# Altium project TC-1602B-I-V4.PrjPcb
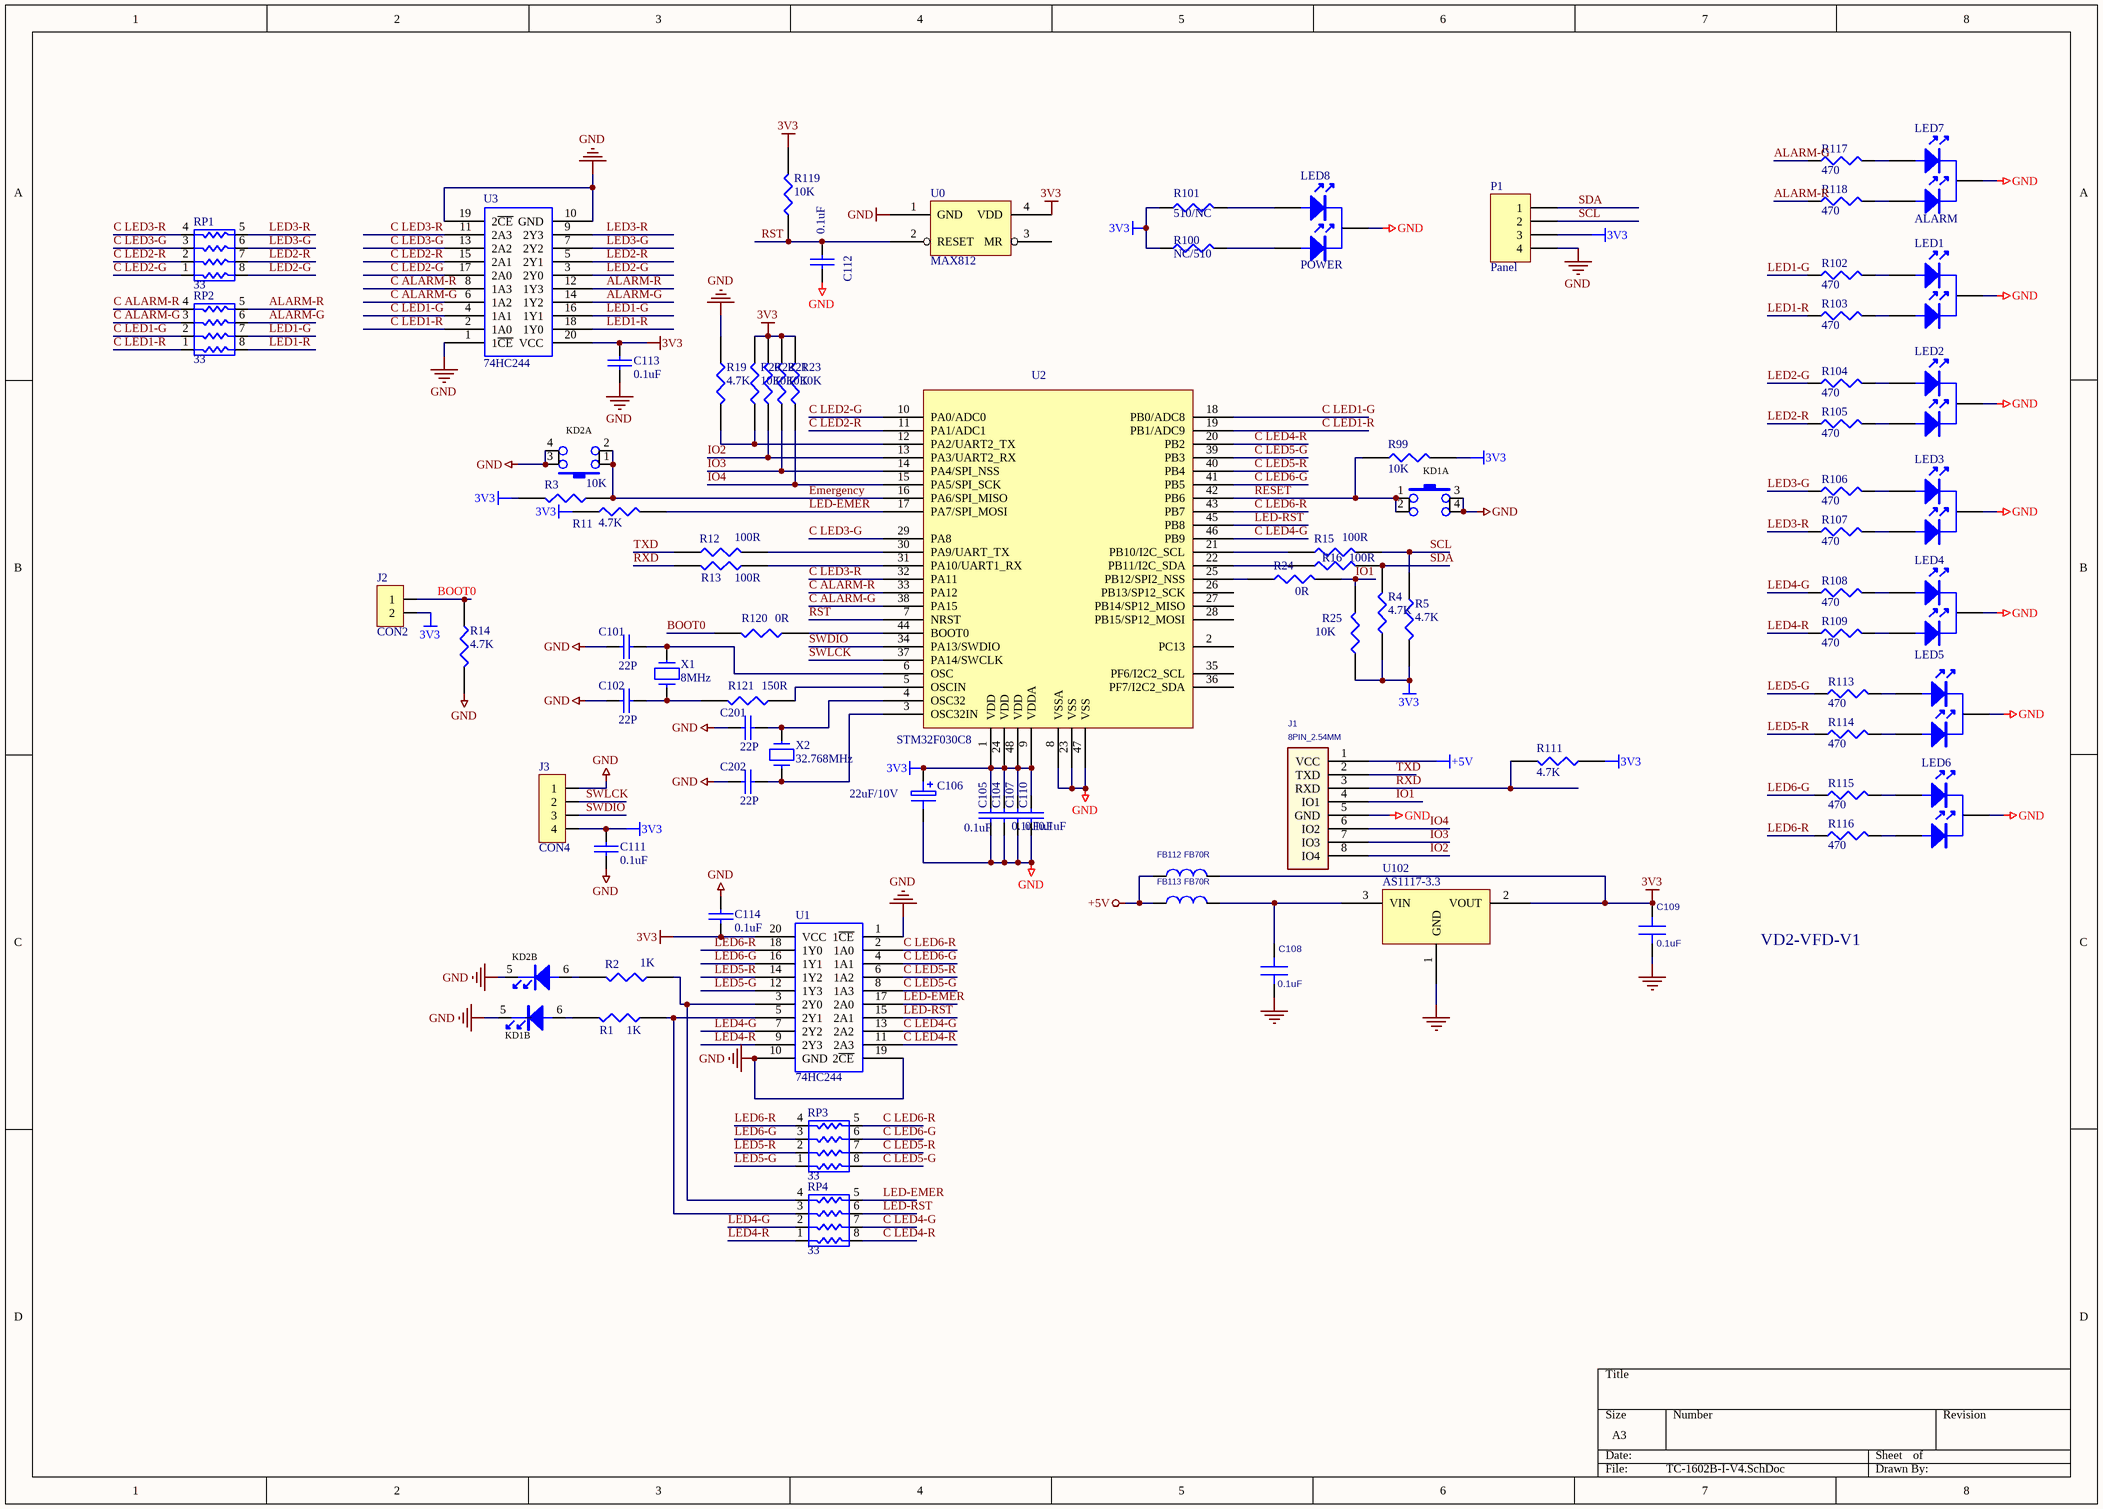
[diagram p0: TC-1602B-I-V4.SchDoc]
1 sheet, 81 parts. Net scope: global (net labels, ports and power ports of the same name join across sheets).

## Sheet TC-1602B-I-V4.SchDoc
size A3; SheetNumber: 0; SheetTotal: 0

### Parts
C101  22P  [C0603]
C102  22P  [C0603]
C104  0.1uF  [C0603]
C105  0.1uF  [C0603]
C106  22uF/10V  [C1206]
C107  0.1uF  [C0603]
C108  0.1uF  [C0402]
C109  0.1uF  [C0603]
C110  0.1uF  [C0603]
C111  0.1uF  [C0603]
C112  0.1uF  [C0603]
C113  0.1uF  [C0603]
C114  0.1uF  [C0603]
C201  22P  [C0402]
C202  22P  [C0402]
FB112  FB70R  [FB0603]
FB113  FB70R  [FB0603]
J1  8PIN_2.54MM  [CON8_2D54MM_G]
J2  CON2  [TJC3-2]
J3  CON4  [TJC3-4]
KD1  RESET  [SW6X6LED1]  (value not drawn)  (parts A,B of 2)
KD2  RESET  [SW6X6LED1]  (value not drawn)  (parts A,B of 2)
LED1  (no value)  [SIP3]
LED2  (no value)  [SIP3]
LED3  (no value)  [SIP3]
LED4  (no value)  [SIP3]
LED5  (no value)  [SIP3]
LED6  (no value)  [SIP3]
LED7  ALARM  [SIP3]
LED8  POWER  [SIP3]
P1  Panel  [Panel]
R1  1K  [R0603]
R2  1K  [R0603]
R3  10K  [R0603]
R4  4.7K  [R0603]
R5  4.7K  [R0603]
R11  4.7K  [R0603]
R12  100R  [R0603]
R13  100R  [R0603]
R14  4.7K  [R0603]
R15  100R  [R0603]
R16  100R  [R0603]
R19  4.7K  [R0603]
R20  10K  [R0603]
R21  10K  [R0603]
R22  10K  [R0603]
R23  10K  [R0603]
R24  0R  [R0603]
R25  10K  [R0603]
R99  10K  [R0603]
R100  NC/510  [R0603]
R101  510/NC  [R0603]
R102  470  [R0603]
R103  470  [R0603]
R104  470  [R0603]
R105  470  [R0603]
R106  470  [R0603]
R107  470  [R0603]
R108  470  [R0603]
R109  470  [R0603]
R111  4.7K  [R0603]
R113  470  [R0603]
R114  470  [R0603]
R115  470  [R0603]
R116  470  [R0603]
R117  470  [R0603]
R118  470  [R0603]
R119  10K  [R0603]
R120  0R  [R0603]
R121  150R  [R0603]
RP1  33  [RP0603]
RP2  33  [RP0603]
RP3  33  [RP0603]
RP4  33  [RP0603]
U0  MAX812  [SOT-143]
U1  74HC244  [SSOP-20]
U2  STM32F030C8  [QFN-48P-ATBM8869]
U3  74HC244  [SSOP-20]
U102  AS1117-3.3  [SOT-223]
X1  8MHz  [X-HC-49S]
X2  32.768MHz  [X-DT38]

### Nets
3V3: C104.1 C105.1 C106.1 C107.1 C109.1 C110.1 C111.1 C113.2 C114.1 FB112.2 J2.2 J3.4 P1.3 R3.2 R4.1 R5.2 R11.1 R20.2 R21.2 R22.2 R23.2 R25.1 R99.2 R100.1 R101.1 R111.1 R119.2 U0.4(VDD) U1.20(VCC) U2.1(VDD) U2.9(VDDA) U2.24(VDD) U2.48(VDD) U3.20(VCC) U102.2(VOUT)
+5V: FB112.1 FB113.1 J1.1(VCC)
GND: C101.1 C102.1 C104.2 C105.2 C106.2 C107.2 C108.2 C109.2 C110.2 C111.2 C112.2 C113.1 C114.2 C201.1 C202.1 J1.5(GND) J3.1 KD1.3 KD1.4 KD1.5 KD2.3 KD2.4 KD2.5 LED1.2 LED2.2 LED3.2 LED4.2 LED5.2 LED6.2 LED7.2 LED8.2 P1.4 R14.2 R19.1 U0.1(GND) U1.1(1~{CE}) U1.10(GND) U1.19(2~{CE}) U2.8(VSSA) U2.23(VSS) U2.47(VSS) U3.1(1~{CE}) U3.10(GND) U3.19(2~{CE}) U102.1(GND)
ALARM-G: R117.1 RP2.6 U3.14(1Y2)
ALARM-R: R118.1 RP2.5 U3.12(1Y3)
BOOT0: J2.1 R14.1 R120.2
C ALARM-G: RP2.3 U2.38(PA15) U3.6(1A2)
C ALARM-R: RP2.4 U2.33(PA12) U3.8(1A3)
C LED1-G: RP2.2 U2.18(PB0/ADC8) U3.4(1A1)
C LED1-R: RP2.1 U2.19(PB1/ADC9) U3.2(1A0)
C LED2-G: RP1.1 U2.10(PA0/ADC0) U3.17(2A0)
C LED2-R: RP1.2 U2.11(PA1/ADC1) U3.15(2A1)
C LED3-G: RP1.3 U2.29(PA8) U3.13(2A2)
C LED3-R: RP1.4 U2.32(PA11) U3.11(2A3)
C LED4-G: RP4.7 U1.13(2A2) U2.46(PB9)
C LED4-R: RP4.8 U1.11(2A3) U2.20(PB2)
C LED5-G: RP3.8 U1.8(1A3) U2.39(PB3)
C LED5-R: RP3.7 U1.6(1A2) U2.40(PB4)
C LED6-G: RP3.6 U1.4(1A1) U2.41(PB5)
C LED6-R: RP3.5 U1.2(1A0) U2.43(PB7)
Emergency: KD2.1 KD2.2 R3.1 U2.16(PA6/SPI_MISO)
IO1: J1.4(IO1) R24.2 R25.2
IO2: J1.8(IO4) R22.1 U2.13(PA3/UART2_RX)
IO3: J1.7(IO3) R21.1 U2.14(PA4/SPI_NSS)
IO4: J1.6(IO2) R23.1 U2.15(PA5/SPI_SCK)
LED1-G: R102.1 RP2.7 U3.16(1Y1)
LED1-R: R103.1 RP2.8 U3.18(1Y0)
LED2-G: R104.1 RP1.8 U3.3(2Y0)
LED2-R: R105.1 RP1.7 U3.5(2Y1)
LED3-G: R106.1 RP1.6 U3.7(2Y2)
LED3-R: R107.1 RP1.5 U3.9(2Y3)
LED4-G: R108.1 RP4.2 U1.7(2Y2)
LED4-R: R109.1 RP4.1 U1.9(2Y3)
LED5-G: R113.1 RP3.1 U1.12(1Y3)
LED5-R: R114.1 RP3.2 U1.14(1Y2)
LED6-G: R115.1 RP3.3 U1.16(1Y1)
LED6-R: R116.1 RP3.4 U1.18(1Y0)
LED-EMER: R11.2 RP4.5 U1.17(2A0) U2.17(PA7/SPI_MOSI)
LED-RST: RP4.6 U1.15(2A1) U2.45(PB8)
RESET: KD1.1 KD1.2 R99.1 U2.42(PB6)
RST: C112.1 R119.1 U0.2(RESET) U2.7(NRST)
RXD: J1.3(RXD) R13.2 R111.2
SCL: P1.2 R5.1 R15.2
SDA: P1.1 R4.2 R16.2
SWDIO: J3.3 U2.34(PA13/SWDIO)
SWLCK: J3.2 U2.37(PA14/SWCLK)
TXD: J1.2(TXD) R12.1
NetC101_2: C101.2 U2.6(OSC) X1.1
NetC102_2: C102.2 R121.2 X1.2
NetC108_1: C108.1 FB113.2 U102.3(VIN)
NetC201_2: C201.2 U2.4(OSC32) X2.1
NetC202_2: C202.2 U2.3(OSC32IN) X2.2
NetKD1_6: KD1.6 R1.2
NetKD2_6: KD2.6 R2.2
NetLED1_1: LED1.1 R102.2
NetLED1_3: LED1.3 R103.2
NetLED2_1: LED2.1 R104.2
NetLED2_3: LED2.3 R105.2
NetLED3_1: LED3.1 R106.2
NetLED3_3: LED3.3 R107.2
NetLED4_1: LED4.1 R108.2
NetLED4_3: LED4.3 R109.2
NetLED5_1: LED5.1 R113.2
NetLED5_3: LED5.3 R114.2
NetLED6_1: LED6.1 R115.2
NetLED6_3: LED6.3 R116.2
NetLED7_1: LED7.1 R117.2
NetLED7_3: LED7.3 R118.2
NetLED8_1: LED8.1 R101.2
NetLED8_3: LED8.3 R100.2
NetR1_1: R1.1 RP4.3 U1.5(2Y1)
NetR2_1: R2.1 RP4.4 U1.3(2Y0)
NetR12_2: R12.2 U2.30(PA9/UART_TX)
NetR13_1: R13.1 U2.31(PA10/UART1_RX)
NetR15_1: R15.1 U2.21(PB10/I2C_SCL)
NetR16_1: R16.1 U2.22(PB11/I2C_SDA)
NetR19_2: R19.2 R20.1 U2.12(PA2/UART2_TX)
NetR24_1: R24.1 U2.25(PB12/SPI2_NSS)
NetR120_1: R120.1 U2.44(BOOT0)
NetR121_1: R121.1 U2.5(OSCIN)

Not connected (* = marked no-connect by the designer): U0 3(MR); U2 2(PC13) 26(PB13/SP12_SCK) 27(PB14/SP12_MISO) 28(PB15/SP12_MOSI) 35(PF6/I2C2_SCL) 36(PF7/I2C2_SDA)

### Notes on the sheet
- VD2-VFD-V1

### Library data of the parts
C101 C102 C104 C105 C107 C110-C114 C201 C202 = CAP
C106 = ELECTRO1
C108 = C_0: C 16V 0.1uF+80%~-20% Y5V 0402(ROHS); PARTS: 1; Part Number: C0104Z16RL-G; PINSWAP: (A,B); LEVEL: STD; PKG_TYPE: SC0603; DEVICE: C1608X7R1H104KT000N; OriginalSymbolOrigin: (0,30); %208%%161%%192%%224%%195%%251%%179%%198%: SMD陶瓷电容; COMPONENT_HIGH_MAX: 0.9MM; %182%%238%%182%%168%%185%%164%%215%%247%%181%%231%%209%%185%(V): 50; %195%%232%%202%%246%: SMD陶瓷电容-50V-100NF-±10%-X7R-0603; CODE: 8070627
C109 = C_0: C 16V 0.1uF+80%~-20% Y5V 0402(ROHS); PARTS: 1; Part Number: C0104Z16RL-G; PINSWAP: (A,B); LEVEL: STD; PKG_TYPE: SC0402; DEVICE: RMEMK105BJ104KV_FR; OriginalSymbolOrigin: (0,30); CODE: 8070614; %195%%232%%202%%246%: SMD陶瓷电容-16V-100NF-±10%-X7R-0402; %182%%238%%182%%168%%185%%164%%215%%247%%181%%231%%209%%185%(V): 16; COMPONENT_HIGH_MAX: 0.6MM; %208%%161%%192%%224%%195%%251%%179%%198%: SMD陶瓷电容
FB112 FB113 = INDUCTOR_0
J1 = CON8_0
J2 = CON3
KD1 KD2 = 轻触开关带灯
LED1-LED8 = LED
P1 = Header 4: Header, 4-Pin
R1-R5 R11-R16 R19-R25 R99-R109 R111 R113-R121 = RES1
RP1-RP4 = RP-8
U0 = MAX811
U1 U3 = 244
U2 = Component_1
U102 = LM1117
X1 X2 = CRYSTAL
